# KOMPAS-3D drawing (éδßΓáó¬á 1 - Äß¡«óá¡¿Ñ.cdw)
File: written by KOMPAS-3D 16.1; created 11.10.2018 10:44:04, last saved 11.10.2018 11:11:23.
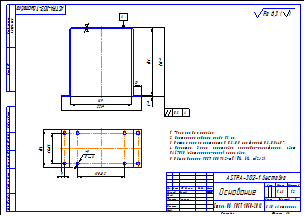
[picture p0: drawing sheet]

Sheet 1: A3, landscape

Title block, sheet 1: name: Основание; designation: ASTRA-302-1 выставка; material: Сталь 08  ГОСТ 1050-2013; mass: 1,43; scale: 1:2; sheets: 1; organisation: ЗАО «Астерион»; sheet format: A3; stored path: Z:\Мембранные насосы\Мембранный электропривод\А302-00.00.000 - ASTRA-302 (МЭ200)\3Д\Выставка\Выставка 1 - Основание.cdw; drawn by: Милов; technical control: Лучихин; drawn by, date: 11.10.2018

Views: Вид 1, Вид:1, Проекционный вид 2
Referenced files in Z:\Мембранные насосы\Мембранный электропривод\А302-00.00.000 - ASTRA-302 (МЭ200)\3Д\Выставка\: Основание.m3d
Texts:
  *Размеры для справок.
  Внутренние радиусы сгиба R3 мм.
  Острые кромки притупить R 0,3...0,5 или фаской 0,3...0,5х45 .
  Покрытие: Эмаль порошковая эпоксидно-полиэфирная, цвет
  RAL7035 (светлосерая-серая), глянцевая.
  Общие допуски ГОСТ 30893.2-mK (H14, h14,  t2/2).
  Ra 6,3
  Ra 6,3 ( )
  ASTRA-302
Dimensions and other numbers on the sheet: 130±0,3; 9; 85±0,3; 104; 8 отв.; 189; 3; 23; 169; 221; 192; 0,3; 1:2; 1; 1,43; 11.10.2018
